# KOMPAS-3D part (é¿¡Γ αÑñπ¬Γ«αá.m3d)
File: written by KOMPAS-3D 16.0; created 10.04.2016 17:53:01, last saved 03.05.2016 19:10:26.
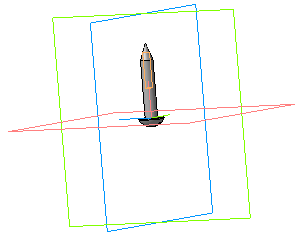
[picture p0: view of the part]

Referenced files in E:\Libs\PartLib\DATA\vault\Methods\Kompas\3D\: PLib_Screw_Shurup_900.m3d
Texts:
  Л63 ГОСТ 15527-2004
  Шуруп 1-3x18.3 ГОСТ 1144-80
  head2
  head4
  groove1
  fillet4
  head3
  groove4
  head5
  fillet1
  groove2
  groove3
  fillet2
  groove5
  head1
  (-) Шуруп 1-3x18.3 ГОСТ 1144-80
